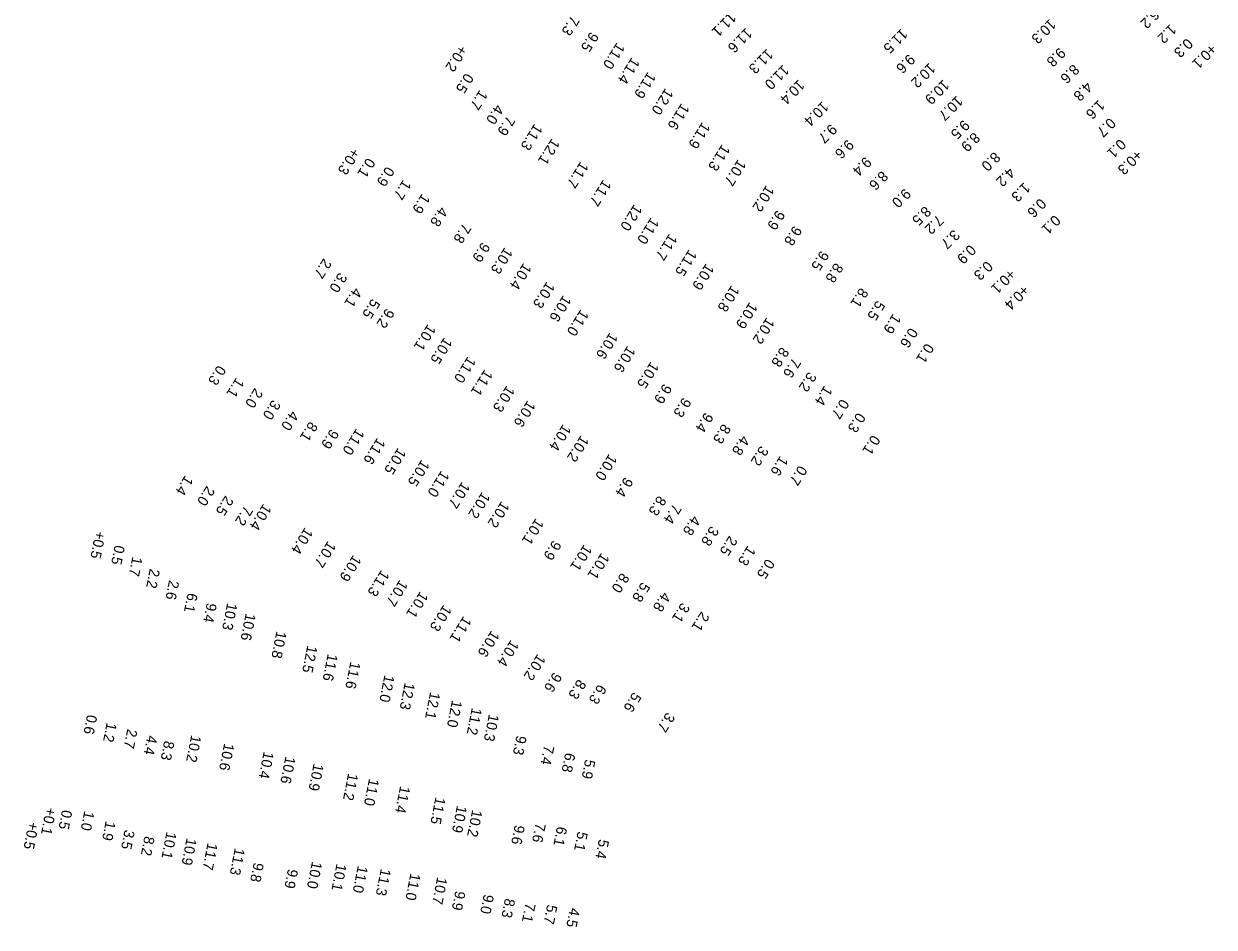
# Model space of a CAD drawing. Extents: x 815385 to 820851, y 582449 to 604245.
# Drawn here: x 816347 to 816918, y 598916 to 599350 of the extents above; entities that cross this region are included whole.
import ezdxf

# ---------------------------------------------------------------- set-up
doc = ezdxf.new("R2010")
doc.units = 0
doc.layers.add('V-TOPO-SOUN-021909', color=7, linetype='Continuous')

msp = doc.modelspace()

# ---------------------------------------------------------------- texts
at = {"layer": 'V-TOPO-SOUN-021909'}
for s, rotation, p in [('7.3', 237.797, (816609.56, 599354.05)), ('11.1 ', 225.026, (816685.72, 599355.75)), ('6.2', 225.026, (816888.82, 599357.15)), ('11.6 ', 225.026, (816693.37, 599348.13)), ('11.5 ', 225.026, (816768, 599347.86)), ('10.3 ', 225.026, (816839.14, 599352.45)), ('1.2', 225.026, (816896.99, 599349.98)), ('9.5', 237.797, (816618.78, 599346.29)), ('0.3', 225.026, (816904.88, 599343.2)), ('+0.2 ', 237.797, (816555.81, 599340)), ('11.0 ', 237.797, (816631.39, 599341.12)), ('11.3 ', 225.026, (816703.46, 599338.07)), ('9.8', 225.026, (816843.77, 599338.75)), ('+0.1 ', 225.026, (816916.33, 599340.53)), ('11.4 ', 237.797, (816638.54, 599334)), ('9.6', 225.026, (816771.54, 599335.62)), ('10.2 ', 225.026, (816781.35, 599331.34)), ('0.5', 237.797, (816558.76, 599326.48)), ('11.9 ', 237.797, (816646.31, 599327.04)), ('11.0 ', 225.026, (816711.1, 599330.46)), ('8.6', 225.026, (816850.38, 599330.75)), ('12.0 ', 237.797, (816654.67, 599319.2)), ('10.4 ', 225.026, (816718.58, 599323.32)), ('10.9 ', 225.026, (816788, 599323.33)), ('4.8', 225.026, (816856.66, 599322.32)), ('1.7', 237.797, (816565.56, 599318.4)), ('10.7 ', 225.026, (816794.52, 599315.59)), ('1.6', 225.026, (816862.61, 599313.64)), ('4.0', 237.797, (816573.29, 599311.51)), ('11.6 ', 237.797, (816662.4, 599311.98)), ('10.4 ', 225.026, (816730.02, 599312.94)), ('7.9', 237.797, (816578.68, 599306.03)), ('11.3 ', 237.797, (816591.91, 599302.18)), ('11.9 ', 237.797, (816672.39, 599302.95)), ('9.5', 225.026, (816797.74, 599304.04)), ('0.7', 225.026, (816867.85, 599305.05)), ('9.7', 225.026, (816734.08, 599302.09)), ('8.9', 225.026, (816802.71, 599298.05)), ('12.1 ', 237.797, (816600.19, 599295.16)), ('11.3 ', 237.797, (816681.89, 599292.27)), ('9.6', 225.026, (816742.13, 599294.67)), ('0.1', 225.026, (816872.77, 599294.89)), ('+0.3 ', 237.797, (816504.21, 599290.62)), ('0.1', 237.797, (816511.56, 599285.85)), ('10.7 ', 237.797, (816689.56, 599285.09)), ('9.4', 225.026, (816750.64, 599286.35)), ('8.0', 225.026, (816812.48, 599288.69)), ('+0.3 ', 225.026, (816880.67, 599289.72)), ('0.9', 237.797, (816520.77, 599281.72)), ('11.7 ', 237.797, (816613.99, 599284.04)), ('8.6', 225.026, (816758.56, 599279.57)), ('4.2', 225.026, (816819.55, 599281.26)), ('1.7', 237.797, (816528.86, 599275.29)), ('11.7 ', 237.797, (816624.88, 599275.34)), ('1.3', 225.026, (816826.85, 599273.96)), ('1.9', 237.797, (816537.9, 599268.61)), ('10.2 ', 237.797, (816703.12, 599272.69)), ('9.0', 225.026, (816769.52, 599271.16)), ('4.8', 237.797, (816546.43, 599262.42)), ('12.0 ', 237.797, (816639.71, 599263.52)), ('8.5', 225.026, (816779.2, 599262.63)), ('0.6', 225.026, (816834.47, 599266.41)), ('11.0 ', 237.797, (816647.77, 599257.14)), ('9.9', 237.797, (816708.2, 599260.78)), ('7.2', 225.026, (816785.3, 599258.39)), ('0.1', 225.026, (816841.37, 599258.39)), ('7.8', 237.797, (816557.61, 599254.38)), ('9.8', 237.797, (816716.33, 599253.28)), ('3.7', 225.026, (816793, 599251.37)), ('9.9', 237.797, (816566.65, 599245.35)), ('11.7 ', 237.797, (816656.57, 599249.37)), ('10.3 ', 237.797, (816577.54, 599242.84)), ('11.5 ', 237.797, (816666, 599241.8)), ('9.5', 237.797, (816729.35, 599241.33)), ('0.9', 225.026, (816800.77, 599244.19)), ('2.7', 237.797, (816490.64, 599237.55)), ('10.4 ', 237.797, (816586.61, 599235.34)), ('10.9 ', 237.797, (816674.2, 599235.11)), ('8.8', 237.797, (816736.17, 599235.47)), ('0.3', 225.026, (816808.82, 599236.33)), ('3.0', 237.797, (816498.05, 599230.78)), ('+0.1 ', 225.026, (816819.83, 599232.55)), ('4.1', 237.797, (816505.26, 599223.63)), ('10.3 ', 237.797, (816597.75, 599226.37)), ('10.8 ', 237.797, (816686.41, 599224.66)), ('8.1', 237.797, (816748.22, 599223.51)), ('+0.4 ', 225.026, (816826.34, 599224.84)), ('5.5', 237.797, (816513.88, 599218.26)), ('10.6 ', 237.797, (816605.68, 599219.89)), ('10.9 ', 237.797, (816695.11, 599216.56)), ('5.5', 237.797, (816756.25, 599217.41)), ('9.2', 237.797, (816520.72, 599213.66)), ('11.0 ', 237.797, (816614.04, 599213.06)), ('1.9', 237.797, (816763.98, 599210.99)), ('10.1 ', 237.797, (816540.64, 599205.97)), ('10.2 ', 237.797, (816703.26, 599209.2)), ('10.5 ', 237.797, (816548.54, 599199.66)), ('10.6 ', 237.797, (816628.05, 599202.03)), ('0.6', 237.797, (816771.99, 599204.34)), ('10.6 ', 237.797, (816636.51, 599195.6)), ('8.8', 237.797, (816710.21, 599195.04)), ('0.1', 237.797, (816779.7, 599196.88)), ('11.0 ', 237.797, (816559.88, 599190.53)), ('10.5 ', 237.797, (816647.68, 599187.96)), ('7.6', 237.797, (816715.84, 599189.86)), ('0.3', 237.797, (816439.87, 599186.32)), ('11.1 ', 237.797, (816567.96, 599184.26)), ('3.2', 237.797, (816723.37, 599183.12)), ('1.1', 237.797, (816448.72, 599180.29)), ('10.3 ', 237.797, (816578.53, 599176.56)), ('9.9', 237.797, (816653.88, 599177.42)), ('1.4', 237.797, (816731.05, 599176.51)), ('2.0', 237.797, (816457.64, 599175.37)), ('9.3', 237.797, (816663.19, 599170.89)), ('3.0', 237.797, (816466.12, 599169.72)), ('10.6 ', 237.797, (816588.54, 599169.37)), ('0.7', 237.797, (816739.02, 599170.13)), ('4.0', 237.797, (816474.91, 599164.56)), ('9.4', 237.797, (816673.79, 599163.69)), ('0.3', 237.797, (816746.87, 599163.59)), ('8.1', 237.797, (816483.94, 599159.31)), ('9.9', 237.797, (816494.08, 599155.72)), ('11.0 ', 237.797, (816506.38, 599155.95)), ('10.4 ', 237.797, (816605.57, 599157.98)), ('8.3', 237.797, (816682.22, 599158.21)), ('11.6 ', 237.797, (816516.43, 599151.45)), ('10.2 ', 237.797, (816614.12, 599152.63)), ('4.8', 237.797, (816691.32, 599152.67)), ('0.1', 237.797, (816753.92, 599152.86)), ('10.5 ', 237.797, (816526.37, 599146.67)), ('10.0 ', 237.797, (816627.65, 599143.72)), ('3.2', 237.797, (816700.34, 599147.63)), ('1.6', 237.797, (816709.8, 599142.81)), ('10.5 ', 237.797, (816537.67, 599140.93)), ('0.7', 237.797, (816718.89, 599138.24)), ('1.4', 237.797, (816424.21, 599133.43)), ('11.0 ', 237.797, (816547.17, 599135.76)), ('9.4', 237.797, (816635.27, 599132.68)), ('2.0', 237.797, (816434.57, 599128.43)), ('10.7 ', 237.797, (816557.07, 599130.36)), ('10.2 ', 237.797, (816566.74, 599125.49)), ('2.5', 237.797, (816443.54, 599123.75)), ('10.4 ', 237.797, (816461.78, 599119.83)), ('10.2 ', 237.797, (816576.04, 599121.08)), ('8.3', 237.797, (816651.26, 599123.73)), ('7.4', 237.797, (816658.5, 599119.79)), ('7.2', 237.797, (816452.81, 599118.92)), ('4.8', 237.797, (816667.74, 599114.2)), ('10.4 ', 237.797, (816481.68, 599108.41)), ('10.1 ', 237.797, (816592.47, 599112.83)), ('3.8', 237.797, (816676.49, 599109.17)), ('+0.5 ', 258.865, (816381.15, 599106.63)), ('9.9', 237.797, (816600.83, 599102.35)), ('2.5', 237.797, (816685.42, 599104.51)), ('0.5', 258.865, (816390.37, 599099.9)), ('10.7 ', 237.797, (816492.73, 599101.93)), ('10.1 ', 237.797, (816615.65, 599100.3)), ('1.3', 237.797, (816694.2, 599099.69)), ('1.7', 258.865, (816398.84, 599094.34)), ('10.9 ', 237.797, (816504.91, 599095.27)), ('10.1 ', 237.797, (816623.99, 599096.3)), ('0.5', 237.797, (816703.27, 599093.45)), ('2.2', 258.865, (816407.21, 599088.59)), ('11.3 ', 237.797, (816518.37, 599088.04)), ('8.0', 237.797, (816633.51, 599086.68)), ('2.6', 258.865, (816416.47, 599083.06)), ('10.7 ', 237.797, (816527.22, 599083.33)), ('5.8', 237.797, (816643.42, 599082.25)), ('6.1', 258.865, (816425.34, 599076.95)), ('10.1 ', 237.797, (816536.98, 599077.74)), ('4.8', 237.797, (816653.38, 599077.58)), ('9.4', 258.865, (816434.53, 599072.18)), ('10.3 ', 258.865, (816444.36, 599072.15)), ('10.3 ', 237.797, (816548.26, 599071.34)), ('3.1', 237.797, (816662.55, 599072.4)), ('2.1', 237.797, (816671.96, 599068.16)), ('10.6 ', 258.865, (816453.24, 599067.15)), ('11.1 ', 237.797, (816557.81, 599065.9)), ('10.8 ', 258.865, (816468.02, 599058.61)), ('10.6 ', 237.797, (816571.23, 599059.04)), ('12.5 ', 258.865, (816482.81, 599051.71)), ('10.4 ', 237.797, (816580.53, 599054.51)), ('11.6 ', 258.865, (816492.62, 599047.73)), ('10.2 ', 237.797, (816593.37, 599047.75)), ('11.6 ', 258.865, (816503.51, 599043.99)), ('12.0 ', 258.865, (816519.84, 599037.6)), ('12.3 ', 258.865, (816529.59, 599033.96)), ('9.6', 237.797, (816601.12, 599039.01)), ('8.3', 237.797, (816612.77, 599035.64)), ('12.1 ', 258.865, (816541.78, 599029.41)), ('6.3', 237.797, (816622.58, 599033.25)), ('5.6', 237.797, (816639.28, 599029.43)), ('12.0 ', 258.865, (816552.28, 599025.48)), ('0.6', 258.865, (816377.12, 599018.54)), ('11.2 ', 258.865, (816561.78, 599021.85)), ('10.3 ', 258.865, (816569.99, 599018.79)), ('3.7', 237.797, (816655.37, 599019.78)), ('1.2', 258.865, (816386.53, 599014.76)), ('2.7', 258.865, (816396.41, 599011.69)), ('4.4', 258.865, (816406.04, 599008.64)), ('8.3', 258.865, (816414.17, 599006.04)), ('10.2 ', 258.865, (816427.1, 599008.75)), ('9.3', 258.865, (816583.23, 599008.57)), ('10.6 ', 258.865, (816442.91, 599004.81)), ('10.4 ', 258.865, (816461.91, 599000.86)), ('7.4', 258.865, (816596.5, 599003.84)), ('6.8', 258.865, (816606.63, 599000.27)), ('10.6 ', 258.865, (816472.31, 598998.5)), ('10.9 ', 258.865, (816485.84, 598995.03)), ('5.9', 258.865, (816616.22, 598997.13)), ('11.2 ', 258.865, (816502.42, 598990.4)), ('11.0 ', 258.865, (816512.45, 598987.87)), ('11.4 ', 258.865, (816527.38, 598984.3)), ('11.5 ', 258.865, (816544.35, 598979)), ('+0.1 ', 258.865, (816357.46, 598974.05)), ('0.5', 258.865, (816365.13, 598972.88)), ('1.0', 258.865, (816375.77, 598972.29)), ('10.9 ', 258.865, (816554.66, 598974.89)), ('10.2 ', 258.865, (816561.98, 598972.9)), ('+0.5 ', 258.865, (816349.1, 598967.15)), ('1.9', 258.865, (816386.03, 598967.48)), ('9.6', 258.865, (816582.4, 598965.61)), ('7.6', 258.865, (816592.43, 598966.61)), ('3.5', 258.865, (816395.13, 598963.31)), ('8.2', 258.865, (816404.66, 598960.24)), ('10.1 ', 258.865, (816415.25, 598962.34)), ('10.9 ', 258.865, (816424.89, 598959.33)), ('6.1', 258.865, (816602.67, 598964.92)), ('5.1', 258.865, (816612.6, 598962.49)), ('11.7 ', 258.865, (816434.96, 598957.02)), ('11.3 ', 258.865, (816448.03, 598954.55)), ('5.4', 258.865, (816622.79, 598958.78)), ('10.0 ', 258.865, (816485.08, 598948.1)), ('9.8', 258.865, (816457.1, 598947.62)), ('9.9', 258.865, (816473.52, 598944.54)), ('10.1 ', 258.865, (816496.86, 598947.04)), ('11.0 ', 258.865, (816507.06, 598946.05)), ('11.3 ', 258.865, (816518.11, 598944.67)), ('11.0 ', 258.865, (816532.34, 598942.49)), ('10.7 ', 258.865, (816545.16, 598940.59)), ('9.9', 258.865, (816553.87, 598934.04)), ('9.0', 258.865, (816567.53, 598932.36)), ('8.3', 258.865, (816577.72, 598930.44)), ('7.1', 258.865, (816587.54, 598928.25)), ('5.7', 258.865, (816597.97, 598927.44)), ('4.5', 258.865, (816608.85, 598925.88))]:
    msp.add_text(s, height=5, rotation=rotation, dxfattribs=at).set_placement(p)

doc.saveas('drawing.dxf')
